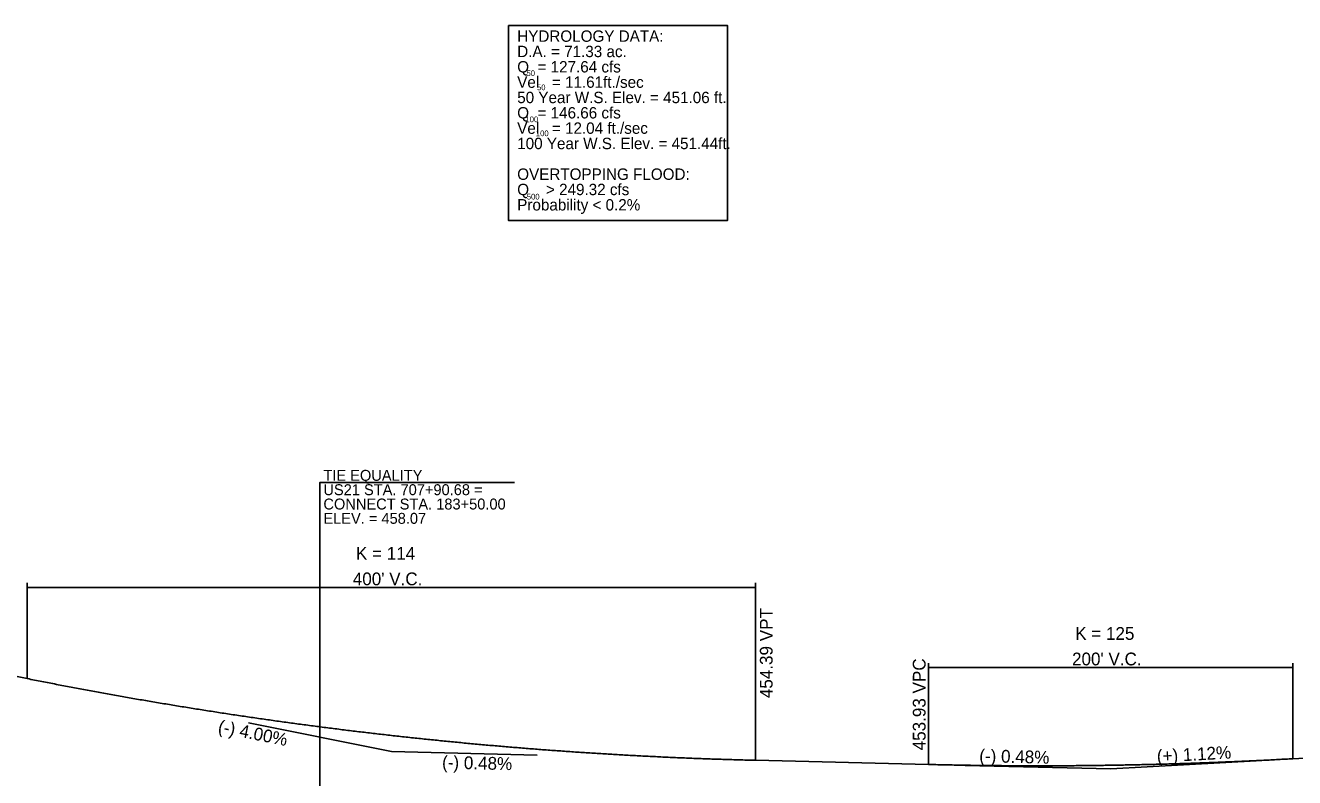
# Model space of a CAD drawing. Extents: x 2017200 to 2047700, y 854850 to 893350.
# Drawn here: x 2023629 to 2024326, y 889412 to 889825 of the extents above; entities that cross this region are included whole.
import ezdxf

# ---------------------------------------------------------------- set-up
doc = ezdxf.new("R2010")
doc.units = 0
for name, color, linetype in [('Default', 7, 'Continuous'), ('RD_DDB_GradeTX', 7, 'Continuous'), ('RD_DDB_Profile_Lbl', 7, 'Continuous'), ('RD_DDB_Profile_PR', 7, 'Continuous'), ('RD_DDB_StripGrade', 7, 'Continuous'), ('RD_DDB_VCLbl', 7, 'Continuous'), ('RD_PD_Final_TX', 7, 'Continuous'), ('RD_PD_NON-PLOTTING', 7, 'Continuous')]:
    doc.layers.add(name, color=color, linetype=linetype)

msp = doc.modelspace()

# ---------------------------------------------------------------- linework, layer by layer
at = {"layer": 'Default'}
msp.add_lwpolyline([(2023894.34, 889825.36), (2024014.48, 889825.36), (2024014.48, 889718.2), (2023894.34, 889718.2)], close=True, dxfattribs=at)
at = {"layer": 'RD_DDB_GradeTX'}
for p, q in [((2023751.55, 889442.49), (2023830, 889426.8)), ((2023909.98, 889424.87), (2023830, 889426.8)), ((2024145.02, 889419.18), (2024225, 889417.25)), ((2024304.88, 889421.7), (2024225, 889417.25))]:
    msp.add_line(p, q, dxfattribs=at)
at = {"layer": 'RD_DDB_Profile_Lbl'}
msp.add_lwpolyline([(2023790.68, 889440.34), (2023790.68, 889574.48), (2023897.51, 889574.48)], dxfattribs=at)
at = {"layer": 'RD_DDB_Profile_PR'}
for p, q in [((2023380, 889516.8), (2023630, 889466.8)), ((2024325, 889422.83), (2025645, 889496.42)), ((2024030, 889421.96), (2024125, 889419.67))]:
    msp.add_line(p, q, dxfattribs=at)
for points in [[(2023630, 889466.8), (2023638, 889465.21), (2023646, 889463.66), (2023654, 889462.13), (2023662, 889460.63), (2023670, 889459.15), (2023678, 889457.71), (2023686, 889456.29), (2023694, 889454.9), (2023702, 889453.54), (2023710, 889452.21), (2023718, 889450.9), (2023726, 889449.63), (2023734, 889448.38), (2023742, 889447.16), (2023750, 889445.96), (2023758, 889444.8), (2023766, 889443.67), (2023774, 889442.56), (2023782, 889441.48), (2023790, 889440.43), (2023798, 889439.4), (2023806, 889438.41), (2023814, 889437.44), (2023822, 889436.5), (2023830, 889435.59), (2023838, 889434.71), (2023846, 889433.85), (2023854, 889433.03), (2023862, 889432.23), (2023870, 889431.46), (2023878, 889430.72), (2023886, 889430), (2023894, 889429.32), (2023902, 889428.66), (2023910, 889428.03), (2023918, 889427.43), (2023926, 889426.86), (2023934, 889426.31), (2023942, 889425.79), (2023950, 889425.31), (2023958, 889424.84), (2023966, 889424.41), (2023974, 889424.01), (2023982, 889423.63), (2023990, 889423.28), (2023998, 889422.96), (2024006, 889422.67), (2024014, 889422.41), (2024022, 889422.17), (2024030, 889421.96)], [(2024125, 889419.67), (2024129, 889419.57), (2024133, 889419.49), (2024137, 889419.41), (2024141, 889419.33), (2024145, 889419.26), (2024149, 889419.2), (2024153, 889419.15), (2024157, 889419.1), (2024161, 889419.06), (2024165, 889419.02), (2024169, 889418.99), (2024173, 889418.97), (2024177, 889418.95), (2024181, 889418.94), (2024185, 889418.94), (2024189, 889418.94), (2024193, 889418.95), (2024197, 889418.96), (2024201, 889418.98), (2024205, 889419.01), (2024209, 889419.05), (2024213, 889419.09), (2024217, 889419.13), (2024221, 889419.19), (2024225, 889419.25), (2024229, 889419.31), (2024233, 889419.39), (2024237, 889419.47), (2024241, 889419.55), (2024245, 889419.64), (2024249, 889419.74), (2024253, 889419.85), (2024257, 889419.96), (2024261, 889420.08), (2024265, 889420.2), (2024269, 889420.33), (2024273, 889420.47), (2024277, 889420.61), (2024281, 889420.76), (2024285, 889420.91), (2024289, 889421.08), (2024293, 889421.25), (2024297, 889421.42), (2024301, 889421.6), (2024305, 889421.79), (2024309, 889421.98), (2024313, 889422.18), (2024317, 889422.39), (2024321, 889422.61), (2024325, 889422.83)]]:
    msp.add_spline(points, degree=3, dxfattribs=at)
at = {"layer": 'RD_DDB_VCLbl'}
for p, q in [((2023630, 889519.3), (2023630, 889466.8)), ((2023630, 889516.8), (2024030, 889516.8)), ((2024030, 889519.3), (2024030, 889421.96)), ((2024125, 889475.33), (2024125, 889419.67)), ((2024125, 889472.83), (2024325, 889472.83)), ((2024325, 889475.33), (2024325, 889422.83))]:
    msp.add_line(p, q, dxfattribs=at)
at = {"layer": 'RD_PD_NON-PLOTTING'}
msp.add_line((2023790.68, 889100), (2023790.68, 889544.4), dxfattribs=at)

# ---------------------------------------------------------------- texts
at = {"layer": 'RD_DDB_GradeTX'}
for s, rotation, p in [('(-) 4.00%', 348.69007, (2023734.36, 889437.29)), ('(-) 0.48%', 358.61502, (2023857.72, 889417.47)), ('(-) 0.48%', 358.61502, (2024152.75, 889421)), ('(+) 1.12%', 3.19108, (2024250.52, 889420.68))]:
    msp.add_text(s, height=7, rotation=rotation, dxfattribs=at).set_placement(p)
at = {"layer": 'RD_DDB_Profile_Lbl'}
for s, p in [('TIE EQUALITY', (2023792.6, 889575.37)), ('US21 STA. 707+90.68 =', (2023792.6, 889567.5)), ('CONNECT STA. 183+50.00', (2023792.6, 889559.63)), ('ELEV. = 458.07', (2023792.6, 889551.77))]:
    msp.add_text(s, height=6, dxfattribs=at).set_placement(p)
at = {"layer": 'RD_DDB_StripGrade'}
for s, p in [('454.39 VPT', (2024039.32, 889456.07)), ('453.93 VPC', (2024123.31, 889427.43))]:
    msp.add_text(s, height=7, rotation=90, dxfattribs=at).set_placement(p)
at = {"layer": 'RD_DDB_VCLbl'}
for s, p in [('K = 114', (2023810.48, 889532.05)), ("400' V.C.", (2023808.75, 889518.05)), ('K = 125', (2024205.48, 889488.08)), ("200' V.C.", (2024203.75, 889474.08))]:
    msp.add_text(s, height=7, dxfattribs=at).set_placement(p)
at = {"layer": 'RD_PD_Final_TX'}
for s, height, p in [('HYDROLOGY DATA:', 6.25, (2023899.05, 889816.36)), ('D.A. = 71.33 ac.', 6.25, (2023899.05, 889807.94)), ('Q  = 127.64 cfs', 6.25, (2023899.05, 889799.52)), ('50', 3.125, (2023904.19, 889797.56)), ('Vel   = 11.61ft./sec', 6.25, (2023899.05, 889791.1)), ('50', 3.125, (2023909.93, 889789.79)), ('50 Year W.S. Elev. = 451.06 ft.', 6.25, (2023899.05, 889782.68)), ('Q  = 146.66 cfs', 6.25, (2023899.05, 889774.27)), ('Vel   = 12.04 ft./sec', 6.25, (2023899.05, 889765.85)), ('100', 3.125, (2023903.59, 889772.22)), ('100', 3.125, (2023909.31, 889764.56)), ('100 Year W.S. Elev. = 451.44ft.', 6.25, (2023899.05, 889757.43)), ('OVERTOPPING FLOOD:', 6.25, (2023899.05, 889740.59)), ('Q    > 249.32 cfs', 6.25, (2023899.05, 889732.18)), ('Probability < 0.2%', 6.25, (2023899.05, 889723.76)), ('500', 3.125, (2023904.34, 889729.8))]:
    msp.add_text(s, height=height, rotation=360, dxfattribs=at).set_placement(p)

doc.saveas('drawing.dxf')
